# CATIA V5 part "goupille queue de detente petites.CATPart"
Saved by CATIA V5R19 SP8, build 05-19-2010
Part number: goupille queue de detente
Bounding box of the stored display mesh (mm): x 0 to 10, y -1 to 1, z -1 to 1
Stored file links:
  C:\Users\Arthur\Desktop\Catia parts\GLOCK\Poignée\goupille queue de detente petites.CATPart
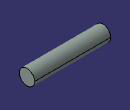
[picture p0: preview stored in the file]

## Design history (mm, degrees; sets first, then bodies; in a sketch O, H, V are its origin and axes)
Set1
  Sketch1 on yz-plane, origin (0, 0, 0), H (0, 1, 0), V (0, 0, 1)
    circle A1 centre (0, 0) radius 1
    radius A1 = 1
Body1 (main body)
  Pad1: profile Sketch1, direction (1, 0, 0), length 10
